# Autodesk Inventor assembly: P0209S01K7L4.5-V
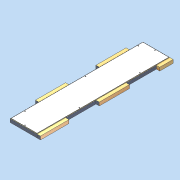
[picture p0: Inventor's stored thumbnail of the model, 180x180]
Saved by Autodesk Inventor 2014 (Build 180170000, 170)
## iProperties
Created: 2011-04
Part Number: P0209S01K7L4.5-V
Document SubType Name: Assembly
Designer: david.appleford
Description: 0.5w x 2.25w 01 Panel - 7 Locks 4.5 Lugs
Mass: 31000 g
Surface Area: 41905.5 cm^2
Volume: 127637 cm^3
Density: 0.242876 g/cm^3
Cost Center: £125.00
Justset: False
Title: 0.5w x 2.25w 01 Panel - 7 Locks 4.5 Lugs
Author: david.appleford
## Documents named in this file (5)
- C:\Documents and Settings\john.everitt\Local Settings\My Documents\Vault\Production MkII\VIRTUAL ELEMENTS\Virtual Walls\Virtual Timber + MgO\P0209S01K7L4.5-V.iam
- C:\Documents and Settings\john.everitt\Local Settings\My Documents\Vault\Production MkII\VIRTUAL ELEMENTS\Virtual Lugs\Superceded Lugs\LA02C3V.ipt
- C:\Documents and Settings\john.everitt\Local Settings\My Documents\Vault\Production MkII\VIRTUAL ELEMENTS\Virtual Lugs\Superceded Lugs\LA02M3V.ipt
- C:\Documents and Settings\john.everitt\Local Settings\My Documents\Vault\Production MkII\Virtual Elements\Virtual Walls\Virtual Timber + MgO\P0209S01K7-V.ipt
- C:\Documents and Settings\john.everitt\Local Settings\My Documents\Vault\Production MkII\VIRTUAL ELEMENTS\Virtual Lugs\Superceded Lugs\LA01C3V.ipt
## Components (6 placed, 4 different names)
1. P0209S01K7-V:1 — Mate:1, Flush:1, Flush:2, Mate:5, Mate:6, Flush:9, Flush:10, Mate:7, Flush:11, Mate:15, Flush:14, Flush:15
2. LA02C3V:1 — Mate:1, Flush:1, Flush:2, Mate:9, Mate:13
3. LA02M3V:5 — Mate:6, Flush:9, Mate:12
4. LA02M3V:2 — Mate:5, Flush:10, Mate:12, Mate:13
5. LA02M3V:4 — Mate:7, Flush:11, Mate:9
6. LA01C3V:1 — Mate:15, Flush:14, Flush:15
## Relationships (15: Mate 8, Flush 7)
- Mate:1: P0209S01K7-V:1 ↔ LA02C3V:1
- Flush:1: P0209S01K7-V:1 ↔ LA02C3V:1
- Flush:2: P0209S01K7-V:1 ↔ LA02C3V:1
- Mate:5: P0209S01K7-V:1 ↔ LA02M3V:2
- Mate:6: P0209S01K7-V:1 ↔ LA02M3V:5
- Flush:9: P0209S01K7-V:1 ↔ LA02M3V:5
- Flush:10: P0209S01K7-V:1 ↔ LA02M3V:2
- Mate:7: P0209S01K7-V:1 ↔ LA02M3V:4
- Flush:11: P0209S01K7-V:1 ↔ LA02M3V:4
- Mate:9: LA02C3V:1 ↔ LA02M3V:4
- Mate:12: LA02M3V:5 ↔ LA02M3V:2
- Mate:13: LA02C3V:1 ↔ LA02M3V:2
- Mate:15: P0209S01K7-V:1 ↔ LA01C3V:1
- Flush:14: P0209S01K7-V:1 ↔ LA01C3V:1
- Flush:15: P0209S01K7-V:1 ↔ LA01C3V:1
## Named parameters: t = 1 mm, Cl = 2 mm
